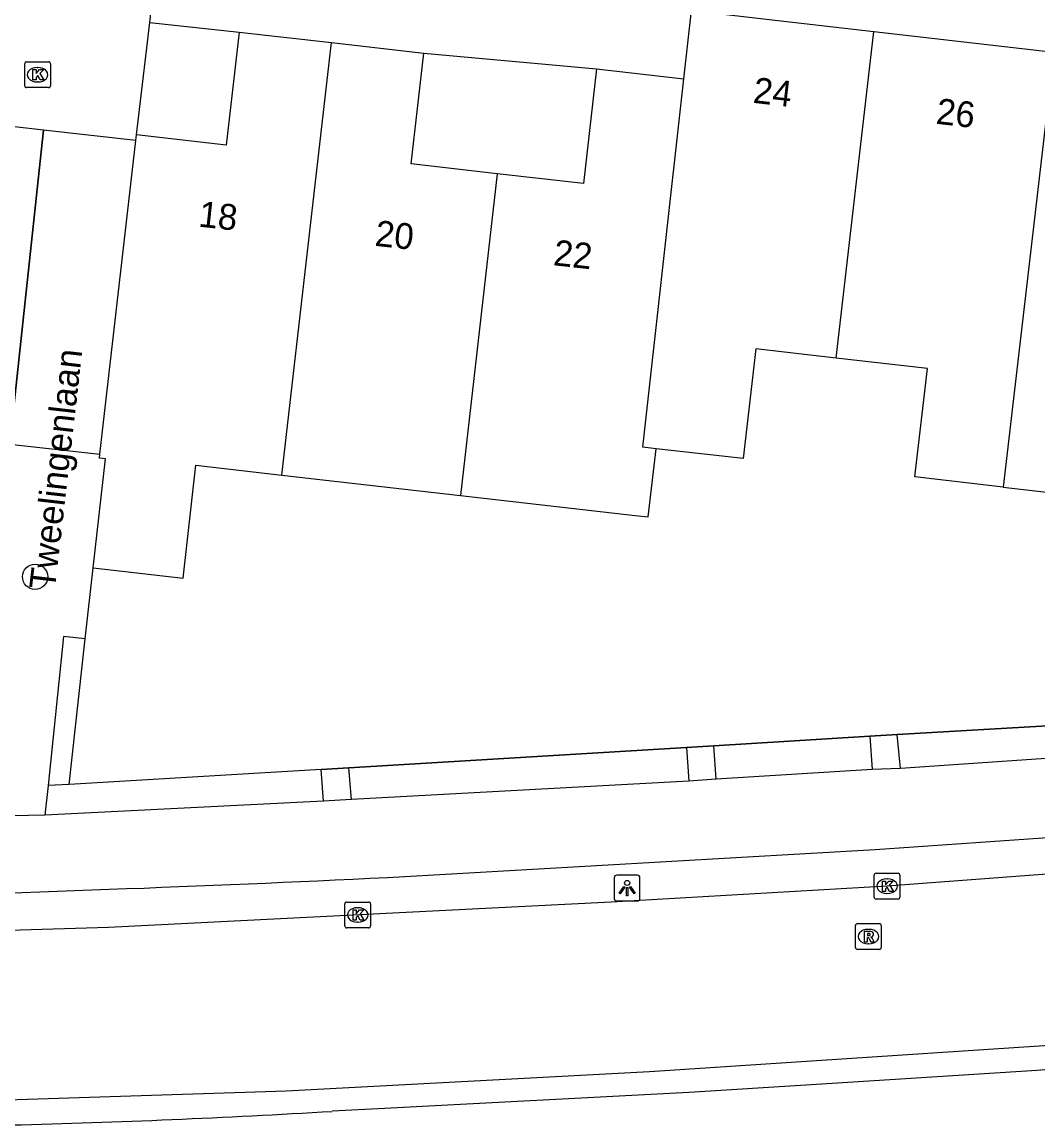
# Model space of a CAD drawing. Extents: x 162398 to 163643, y 386453 to 387397.
# Drawn here: x 162673.7 to 162713.09, y 386454.99 to 386497.76 of the extents above; entities that cross this region are included whole.
import ezdxf

# ---------------------------------------------------------------- set-up
doc = ezdxf.new("R2010")
doc.units = 0
for name, color, linetype in [('IMGEO_Berm_groen', 7, 'Continuous'), ('IMGEO_Boom', 7, 'Continuous'), ('IMGEO_Fietspad_gesloten', 7, 'Continuous'), ('IMGEO_Groenvoorziening', 7, 'Continuous'), ('IMGEO_Kolk', 7, 'Continuous'), ('IMGEO_Lichtpunt', 7, 'Continuous'), ('IMGEO_Muur', 7, 'Continuous'), ('IMGEO_Openbare_ruimte_label', 7, 'Continuous'), ('IMGEO_Pand', 7, 'Continuous'), ('IMGEO_Pand_nummerreeks', 7, 'Continuous'), ('IMGEO_Pand_overbouw', 7, 'Continuous'), ('IMGEO_Rijbaan_lokaal_open', 7, 'Continuous'), ('IMGEO_Rijbaan_regionaal_gesloten', 7, 'Continuous'), ('IMGEO_Rioolput', 7, 'Continuous'), ('IMGEO_Voetpad_open', 7, 'Continuous')]:
    doc.layers.add(name, color=color, linetype=linetype)

msp = doc.modelspace()

# ---------------------------------------------------------------- linework, layer by layer
at = {"layer": 'IMGEO_Berm_groen'}
for points in [[(162707.634, 386470.126), (162713.9, 386470.497)], [(162700.524, 386469.694), (162706.572, 386470.062)], [(162686.376, 386468.838), (162699.459, 386469.63)], [(162685.297, 386468.773), (162675.534, 386468.191)], [(162675.534, 386468.191), (162674.712, 386468.15)]]:
    msp.add_lwpolyline(points, dxfattribs=at)
at = {"layer": 'IMGEO_Boom'}
msp.add_circle((162674.209, 386476.249), 0.489, dxfattribs=at)
at = {"layer": 'IMGEO_Fietspad_gesloten'}
for points in [[(162713.97, 386469.239), (162707.758, 386468.81)], [(162706.663, 386468.77), (162700.617, 386468.394)], [(162707.758, 386468.81), (162706.663, 386468.77)], [(162699.554, 386468.328), (162686.477, 386467.606)], [(162700.617, 386468.394), (162699.554, 386468.328)], [(162687.87, 386464.589), (162706.775, 386465.668), (162723.122, 386466.805), (162738.704, 386468.027)], [(162685.391, 386467.551), (162674.593, 386466.997)], [(162686.477, 386467.606), (162685.391, 386467.551)], [(162674.593, 386466.997), (162655.671, 386466.609), (162655.276, 386466.693)]]:
    msp.add_lwpolyline(points, dxfattribs=at)
msp.add_arc((162642.685, 387395.376), 931.884, 271.451743, 272.779253, dxfattribs=at)
at = {"layer": 'IMGEO_Groenvoorziening'}
msp.add_lwpolyline([(162675.534, 386468.191), (162676.157, 386473.844)], dxfattribs=at)
at = {"layer": 'IMGEO_Kolk'}
for p, q in [((162673.807, 386495.295), (162673.807, 386496.147)), ((162673.882, 386496.221), (162674.734, 386496.221)), ((162674.295, 386496.001), (162674.32, 386496.001)), ((162674.808, 386496.147), (162674.808, 386495.295)), ((162674.734, 386495.221), (162673.882, 386495.221)), ((162674.318, 386495.441), (162674.293, 386495.441)), ((162706.74, 386463.822), (162706.74, 386464.674)), ((162706.815, 386464.748), (162707.667, 386464.748)), ((162707.741, 386464.674), (162707.741, 386463.822)), ((162707.228, 386464.528), (162707.253, 386464.528)), ((162707.251, 386463.968), (162707.226, 386463.968)), ((162686.216, 386462.707), (162686.216, 386463.559)), ((162686.291, 386463.633), (162687.143, 386463.633)), ((162686.704, 386463.413), (162686.729, 386463.413)), ((162687.217, 386463.559), (162687.217, 386462.707)), ((162707.667, 386463.748), (162706.815, 386463.748)), ((162687.143, 386462.633), (162686.291, 386462.633)), ((162686.727, 386462.853), (162686.702, 386462.853))]:
    msp.add_line(p, q, dxfattribs=at)
for points in [[(162673.807, 386495.295), (162673.807, 386496.147)], [(162673.882, 386496.221), (162674.734, 386496.221)], [(162674.128, 386495.921), (162674.251, 386495.921), (162674.251, 386495.77), (162674.381, 386495.921), (162674.545, 386495.921), (162674.399, 386495.77), (162674.552, 386495.521), (162674.4, 386495.521), (162674.315, 386495.685), (162674.251, 386495.618), (162674.251, 386495.521), (162674.128, 386495.521), (162674.128, 386495.921)], [(162674.808, 386496.147), (162674.808, 386495.295)], [(162674.734, 386495.221), (162673.882, 386495.221)], [(162706.74, 386463.822), (162706.74, 386464.674)], [(162706.815, 386464.748), (162707.667, 386464.748)], [(162707.741, 386464.674), (162707.741, 386463.822)], [(162707.061, 386464.448), (162707.184, 386464.448), (162707.184, 386464.297), (162707.314, 386464.448), (162707.478, 386464.448), (162707.332, 386464.297), (162707.485, 386464.048), (162707.333, 386464.048), (162707.248, 386464.212), (162707.184, 386464.145), (162707.184, 386464.048), (162707.061, 386464.048), (162707.061, 386464.448)], [(162686.216, 386462.707), (162686.216, 386463.559)], [(162686.291, 386463.633), (162687.143, 386463.633)], [(162687.217, 386463.559), (162687.217, 386462.707)], [(162707.667, 386463.748), (162706.815, 386463.748)], [(162686.537, 386463.333), (162686.66, 386463.333), (162686.66, 386463.182), (162686.79, 386463.333), (162686.954, 386463.333), (162686.808, 386463.182), (162686.961, 386462.933), (162686.809, 386462.933), (162686.724, 386463.097), (162686.66, 386463.03), (162686.66, 386462.933), (162686.537, 386462.933), (162686.537, 386463.333)], [(162687.143, 386462.633), (162686.291, 386462.633)]]:
    msp.add_lwpolyline(points, dxfattribs=at)
for centre, start, end in [((162673.884, 386496.145), 91.552, 178.448), ((162673.884, 386496.145), 91.552, 178.448), ((162674.732, 386496.145), 1.552, 88.448), ((162674.732, 386496.145), 1.552, 88.448), ((162673.884, 386495.297), 181.552, 268.448), ((162673.884, 386495.297), 181.552, 268.448), ((162674.732, 386495.297), 271.552, 358.448), ((162674.732, 386495.297), 271.552, 358.448), ((162706.817, 386464.672), 91.552, 178.448), ((162706.817, 386464.672), 91.552, 178.448), ((162707.665, 386464.672), 1.552, 88.448), ((162707.665, 386464.672), 1.552, 88.448), ((162706.817, 386463.824), 181.552, 268.448), ((162706.817, 386463.824), 181.552, 268.448), ((162707.665, 386463.824), 271.552, 358.448), ((162707.665, 386463.824), 271.552, 358.448), ((162686.293, 386463.557), 91.552, 178.448), ((162686.293, 386463.557), 91.552, 178.448), ((162687.141, 386463.557), 1.552, 88.448), ((162687.141, 386463.557), 1.552, 88.448), ((162686.293, 386462.709), 181.552, 268.448), ((162686.293, 386462.709), 181.552, 268.448), ((162687.141, 386462.709), 271.552, 358.448), ((162687.141, 386462.709), 271.552, 358.448)]:
    msp.add_arc(centre, 0.0765, start, end, dxfattribs=at)
for centre, major_axis, ratio, start_param, end_param in [((162674.294, 386495.721), (-0.387, 0.002), 0.722429, 4.712389, 7.853982), ((162674.319, 386495.721), (-0.39, 0.002), 0.717154, 1.570796, 4.712389), ((162707.227, 386464.248), (-0.387, 0.002), 0.722429, 4.712389, 7.853982), ((162707.252, 386464.248), (-0.39, 0.002), 0.717154, 1.570796, 4.712389), ((162686.703, 386463.133), (-0.387, 0.002), 0.722429, 4.712389, 7.853982), ((162686.728, 386463.133), (-0.39, 0.002), 0.717154, 1.570796, 4.712389)]:
    msp.add_ellipse(centre, major_axis=major_axis, ratio=ratio, start_param=start_param, end_param=end_param, dxfattribs=at)
at = {"layer": 'IMGEO_Lichtpunt'}
for p, q in [((162697.567, 386464.672), (162696.759, 386464.672)), ((162697.567, 386464.672), (162696.759, 386464.672)), ((162696.665, 386464.577), (162696.665, 386463.77)), ((162696.665, 386464.577), (162696.665, 386463.77)), ((162697.661, 386463.77), (162697.661, 386464.577)), ((162697.661, 386463.77), (162697.661, 386464.577)), ((162696.759, 386463.676), (162697.567, 386463.676)), ((162696.759, 386463.676), (162697.567, 386463.676))]:
    msp.add_line(p, q, dxfattribs=at)
for points in [[(162697.039, 386464.241), (162697.078, 386464.213), (162696.89, 386463.951), (162696.852, 386463.978), (162697.039, 386464.241)], [(162697.251, 386464.213), (162697.289, 386464.24), (162697.476, 386463.978), (162697.437, 386463.95), (162697.251, 386464.213)], [(162697.141, 386464.193), (162697.188, 386464.193), (162697.188, 386463.871), (162697.141, 386463.871), (162697.141, 386464.193)]]:
    msp.add_lwpolyline(points, dxfattribs=at)
msp.add_circle((162697.164, 386464.375), 0.0994, dxfattribs=at)
for centre, start, end in [((162696.759, 386464.577), 90, 180), ((162696.759, 386464.577), 90, 180), ((162697.567, 386464.577), 0, 90), ((162697.567, 386464.577), 0, 90), ((162696.759, 386463.77), 180, 270), ((162696.759, 386463.77), 180, 270), ((162697.567, 386463.77), 270, 0), ((162697.567, 386463.77), 270, 360)]:
    msp.add_arc(centre, 0.0946, start, end, dxfattribs=at)
at = {"layer": 'IMGEO_Muur'}
for points in [[(162676.157, 386473.844), (162676.46, 386476.598)], [(162685.297, 386468.773), (162675.534, 386468.191), (162676.157, 386473.844)], [(162713.9, 386470.497), (162707.634, 386470.126)], [(162706.572, 386470.062), (162700.524, 386469.694)], [(162707.634, 386470.126), (162706.572, 386470.062)], [(162699.459, 386469.63), (162686.376, 386468.838)], [(162700.524, 386469.694), (162699.459, 386469.63)], [(162686.376, 386468.838), (162685.297, 386468.773)]]:
    msp.add_lwpolyline(points, dxfattribs=at)
at = {"layer": 'IMGEO_Pand'}
for points in [[(162699.359, 386495.567), (162699.661, 386498.206), (162703.573, 386497.758), (162706.733, 386497.396)], [(162682.125, 386497.376), (162681.623, 386492.992), (162678.137, 386493.391)], [(162682.125, 386497.376), (162685.702, 386496.966)], [(162705.271, 386484.727), (162706.733, 386497.396)], [(162706.733, 386497.396), (162713.711, 386496.597)], [(162683.78, 386480.194), (162685.702, 386496.966)], [(162685.702, 386496.966), (162689.278, 386496.557)], [(162692.129, 386491.883), (162688.786, 386492.266), (162689.278, 386496.557)], [(162713.711, 386496.597), (162711.749, 386479.729)], [(162695.978, 386495.954), (162695.468, 386491.501), (162692.129, 386491.883)], [(162695.978, 386495.954), (162699.359, 386495.567)], [(162698.283, 386481.217), (162697.769, 386481.276), (162699.359, 386495.567)], [(162676.718, 386481), (162678.111, 386493.167), (162678.137, 386493.391)], [(162692.129, 386491.883), (162690.7, 386479.402)], [(162711.749, 386479.729), (162715.573, 386479.291), (162716.061, 386483.551), (162719.497, 386483.158), (162720.212, 386489.399)], [(162705.271, 386484.727), (162702.148, 386485.085), (162701.66, 386480.83), (162698.283, 386481.217)], [(162711.749, 386479.729), (162708.323, 386480.121), (162708.804, 386484.322), (162705.271, 386484.727)], [(162676.46, 386476.598), (162676.944, 386480.821), (162676.701, 386480.849), (162676.718, 386481)], [(162690.7, 386479.402), (162697.474, 386478.626), (162697.979, 386478.568), (162698.283, 386481.217)], [(162676.46, 386476.598), (162679.946, 386476.199), (162680.447, 386480.576), (162683.78, 386480.194)], [(162683.78, 386480.194), (162690.7, 386479.402)]]:
    msp.add_lwpolyline(points, dxfattribs=at)
at = {"layer": 'IMGEO_Pand_overbouw'}
for points in [[(162674.534, 386493.571), (162671.145, 386493.953), (162670.914, 386491.872), (162670.493, 386488.084), (162669.791, 386481.774), (162672.948, 386481.421), (162673.225, 386481.39)], [(162674.534, 386493.571), (162673.225, 386481.39), (162676.718, 386481), (162678.111, 386493.167)]]:
    msp.add_lwpolyline(points, close=True, dxfattribs=at)
at = {"layer": 'IMGEO_Rijbaan_lokaal_open'}
for points in [[(162678.661, 386497.746), (162679.454, 386504.83)], [(162678.137, 386493.391), (162678.661, 386497.746)], [(162678.661, 386497.746), (162682.125, 386497.376)], [(162689.278, 386496.557), (162695.978, 386495.954)], [(162673.225, 386481.39), (162676.718, 386481)]]:
    msp.add_lwpolyline(points, dxfattribs=at)
at = {"layer": 'IMGEO_Rijbaan_regionaal_gesloten'}
for points in [[(162738.894, 386466.632), (162707.241, 386464.248), (162696.541, 386463.625), (162677.057, 386462.649), (162666.342, 386462.323)], [(162735.421, 386459.09), (162727.225, 386458.269), (162713.042, 386457.097), (162704.301, 386456.543), (162699.562, 386456.243), (162687.757, 386455.622), (162685.732, 386455.516)], [(162663.064, 386455.639), (162683.946, 386456.306), (162698.037, 386457.061), (162718.633, 386458.415)]]:
    msp.add_lwpolyline(points, dxfattribs=at)
msp.add_arc((162664.034, 386819.844), 364.974, 271.45438, 273.40835, dxfattribs=at)
at = {"layer": 'IMGEO_Rioolput'}
for p, q in [((162706.017, 386461.869), (162706.017, 386462.721)), ((162706.092, 386462.795), (162706.944, 386462.795)), ((162706.505, 386462.575), (162706.53, 386462.575)), ((162707.018, 386462.721), (162707.018, 386461.869)), ((162706.944, 386461.795), (162706.092, 386461.795)), ((162706.528, 386462.015), (162706.503, 386462.015))]:
    msp.add_line(p, q, dxfattribs=at)
for points in [[(162706.017, 386461.869), (162706.017, 386462.721)], [(162706.092, 386462.795), (162706.944, 386462.795)], [(162707.018, 386462.721), (162707.018, 386461.869)], [(162706.606, 386462.493), (162706.354, 386462.495), (162706.354, 386462.095)], [(162706.354, 386462.095), (162706.478, 386462.095), (162706.478, 386462.257), (162706.489, 386462.257)], [(162706.532, 386462.414), (162706.478, 386462.414), (162706.478, 386462.333)], [(162706.478, 386462.333), (162706.53, 386462.333)], [(162706.536, 386462.228), (162706.607, 386462.095), (162706.747, 386462.095), (162706.682, 386462.221)], [(162706.944, 386461.795), (162706.092, 386461.795)]]:
    msp.add_lwpolyline(points, dxfattribs=at)
for centre, radius, start, end in [((162706.094, 386462.719), 0.0765, 91.552, 178.448), ((162706.094, 386462.719), 0.0765, 91.552, 178.448), ((162706.942, 386462.719), 0.0765, 1.552, 88.448), ((162706.942, 386462.719), 0.0765, 1.552, 88.448), ((162706.488, 386462.204), 0.0533, 26.0293, 88.6989), ((162706.514, 386462.522), 0.19, 274.7715, 282.9687), ((162706.538, 386462.318), 0.0964, 77.0061, 93.1865), ((162706.552, 386462.375), 0.0378, 276.6634, 79.6772), ((162706.605, 386462.383), 0.109, 350.3612, 89.416), ((162706.603, 386462.383), 0.112, 277.5842, 350.9817), ((162706.587, 386462.168), 0.108, 29.5134, 73.7905), ((162706.094, 386461.871), 0.0765, 181.552, 268.448), ((162706.094, 386461.871), 0.0765, 181.552, 268.448), ((162706.942, 386461.871), 0.0765, 271.552, 358.448), ((162706.942, 386461.871), 0.0765, 271.552, 358.448)]:
    msp.add_arc(centre, radius, start, end, dxfattribs=at)
for centre, major_axis, ratio, start_param, end_param in [((162706.504, 386462.295), (-0.387, 0.002), 0.722429, 4.712389, 7.853982), ((162706.529, 386462.295), (-0.39, 0.002), 0.717154, 1.570796, 4.712389)]:
    msp.add_ellipse(centre, major_axis=major_axis, ratio=ratio, start_param=start_param, end_param=end_param, dxfattribs=at)
at = {"layer": 'IMGEO_Voetpad_open'}
for points in [[(162676.157, 386473.844), (162676.46, 386476.598)], [(162676.157, 386473.844), (162675.31, 386473.932), (162674.712, 386468.15)], [(162706.572, 386470.062), (162707.634, 386470.126)], [(162706.572, 386470.062), (162706.663, 386468.77)], [(162707.758, 386468.81), (162707.634, 386470.126)], [(162699.459, 386469.63), (162700.524, 386469.694)], [(162699.459, 386469.63), (162699.554, 386468.328)], [(162700.617, 386468.394), (162700.524, 386469.694)], [(162685.297, 386468.773), (162686.376, 386468.838)], [(162685.391, 386467.551), (162685.297, 386468.773)], [(162686.477, 386467.606), (162686.376, 386468.838)], [(162674.712, 386468.15), (162674.593, 386466.997)]]:
    msp.add_lwpolyline(points, dxfattribs=at)

# ---------------------------------------------------------------- texts
at = {"layer": 'IMGEO_Openbare_ruimte_label'}
msp.add_text('Tweelingenlaan', height=1, rotation=83.4574, dxfattribs=at).set_placement((162674.974, 386475.717))
at = {"layer": 'IMGEO_Pand_nummerreeks'}
for s, rotation, p in [('24', 353.4683, (162702.015, 386494.635)), ('26', 353.4673, (162709.11, 386493.823)), ('18', 353.7891, (162680.518, 386489.833)), ('20', 353.7891, (162687.354, 386489.089)), ('22', 353.7891, (162694.274, 386488.335))]:
    msp.add_text(s, height=1, rotation=rotation, dxfattribs=at).set_placement(p)

doc.saveas('drawing.dxf')
